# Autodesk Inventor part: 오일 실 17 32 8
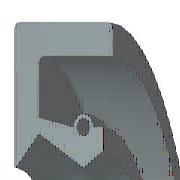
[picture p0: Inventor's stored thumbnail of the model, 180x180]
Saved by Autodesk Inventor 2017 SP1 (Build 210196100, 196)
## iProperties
IsCustomPart: 0
Created: 2018-09
Part Number: 오일 실 17 32 8
Material: 고무
Description: 오일-실
Document SubType Name: Modeling
Standard: KS B 2804
Standards Organization: KS
Language: ko-KR
Size Designation: D - 17 32 8
Categories: <MemberInstance><Categories><Category DisplayName="샤프트 부품" InternalName="7f7aeb1f-a693-4053-b835-cee3144e0d98" Mnemonic="SHFT"><Category DisplayName="실링" Intern
Density: 0.93 g/cm^3
Appearance: 고무 - 검은색 - 버전 1.1
Mass: 2.28027 g
Surface Area: 32.1224 cm^2
Volume: 2.45191 cm^3
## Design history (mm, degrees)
revolve "본체" stored, may be unused: angle "d17" = 90 deg
revolve "스프링1" stored, may be unused: angle "d18" = 90 deg
body "Solid1"
sketch "스케치1"
  geometry: L1 (0, 16)-(8, 16); L2 (8, 14.25)-(1.75, 14.25); L3 (1.75, 10.25)-(4.9, 8.5); L4 (4.9, 8.5)-(0, 8.5); L5 (0, 0)-(9.586, 0) reference; L6 (4.9, 8.5)-(6.3, 9.375); L7 (0, 18)-(0, -3) reference; L8 (-1.941, 0)-(11.507, 0) reference; L9 (4.2, 10.6)-(1.75, 11.21); L10 (1.75, 11.21)-(1.75, 14.25); L11 (0, 16)-(0, 8.588); L12 (4.9, 8.5)-(0, 8.5); L13 (1.75, 10.25)-(0.152, 8.528); L14 (8, 16)-(8, 14.25); L15 (5.6, 10.6)-(6.3, 10.6); L16 (6.3, 10.6)-(6.3, 9.375); C1 r 0.455 at (4.9, 10.6); A1 r 0.7 centre (4.9, 10.6) between (5.6, 10.6) and (4.2, 10.6); A2 r 0.088 centre (0.088, 8.588) between (0, 8.588) and (0.152, 8.528); 1 further point
  constraints: 28 end point, 5 horizontal alignment, 5 point on line, 4 point on circle, 4 vertical alignment, 3 centre point, 3 tangent, 2 collinear, 2 horizontal, 2 perpendicular, 1 coincident, 1 parallel
  dimensions: "d0" = 32 diameter of L1 L5 (= SD2); "d1" = 1.75 distance of L1.end L2.start (= SD); "d2" = 0.91 diameter of C1 (= SPDI); "d3" = 1.4 diameter of A1 (= SPDA); "d4" = 17 diameter of L3.end L5 (= NND); "d5" = 20.5 diameter of L3.start L5 (= TKDM); "d7" = 22.42 diameter of L9.end L5 (= TKDM + 0.24 x SWDT); "d8" = 1.75 distance between parallel lines of L11 L10 (= SD); "d9" = 4.9 distance from line of L11 C1.centre (= SPDST); "d10" = 21.2 diameter of C1.centre L5 (= HLDM); "d11" = 0.0875 radius of A2 (= 0.25 x LAB); "d12" = 6.3 distance between parallel lines of L11 L16 (= SDI); "d13" = 18.75 diameter of L6.end L5 (= ABDM); "d14" = 8 distance from line of L11 L1.end (= SWDT)
fillet "모깎기1" dims "d6" = 0.3 (= RR)
other parameters: "SD2" = 32 [user parameter; used in 1 equation term], "SWDT" = 8 [user parameter; used in 2 equation terms], "RR" = 0.3 [user parameter; used in 1 equation term], "SD" = 1.75 [user parameter; used in 2 equation terms], "NND" = 17 [user parameter; used in 1 equation term], "SPDA" = 1.4 [user parameter; used in 1 equation term], "SPDI" = 0.91 [user parameter; used in 1 equation term], "TKDM" = 20.5 [user parameter; used in 2 equation terms], "HLDM" = 21.2 [user parameter; used in 1 equation term], "ABDM" = 18.75 [user parameter; used in 1 equation term], "SDI" = 6.3 [user parameter; used in 1 equation term], "SPDST" = 4.9 [user parameter; used in 1 equation term], "LAB" = 0.35 [user parameter; used in 1 equation term], "d15" = 0, "d16" = 0, "d19" = 0
